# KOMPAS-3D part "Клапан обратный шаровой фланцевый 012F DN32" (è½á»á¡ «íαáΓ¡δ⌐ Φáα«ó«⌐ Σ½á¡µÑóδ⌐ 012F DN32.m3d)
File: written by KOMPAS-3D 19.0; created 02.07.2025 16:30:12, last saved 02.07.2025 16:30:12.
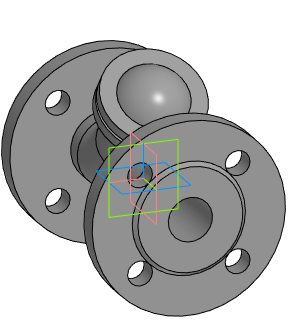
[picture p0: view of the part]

Document properties: Полное имя файла: E:\Dendor Работа Сачек\3D для проектировщиков\5.3 Тип 012F, 012F.Z Клапан обратный шаровой фланцевый\stp_Клапан обратный шаровой фланцевый 012F\Клапан обратный шаровой фланцевый 012F DN32.m3d

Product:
- Part/product: Клапан обратный шаровой фланцевый 012F DN32

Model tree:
1. Операция без истории:1  (labels: Клапан обратный шаровой фланцевый 012F DN32)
